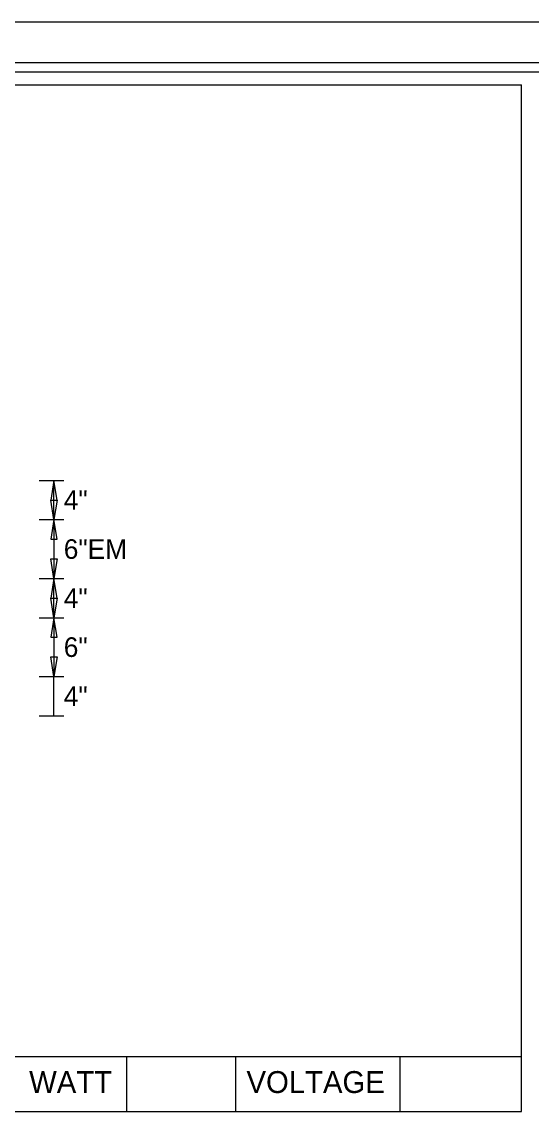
# Model space of a CAD drawing. Extents: x 1374 to 1480, y 568 to 638.
# Drawn here: x 1423.92 to 1428.25, y 595.3 to 604.64 of the extents above; entities that cross this region are included whole.
import ezdxf

# ---------------------------------------------------------------- set-up
doc = ezdxf.new("R2010")
doc.units = 0
for name, color, linetype in [('GSDims', 7, 'Continuous'), ('PlotBorder_dp', 7, 'Continuous'), ('SheetBorder_dp', 7, 'Continuous'), ('SheetLinesMisc2_dp', 7, 'Continuous'), ('TextMinor', 7, 'Continuous')]:
    doc.layers.add(name, color=color, linetype=linetype)

msp = doc.modelspace()

# ---------------------------------------------------------------- linework, layer by layer
at = {"layer": 'GSDims'}
for p, q in [((1424.0665, 600.7496), (1424.2748, 600.7496)), ((1424.0665, 600.7496), (1424.0665, 600.7496)), ((1424.1915, 600.4162), (1424.1915, 600.7496)), ((1424.0665, 600.4162), (1424.2748, 600.4162)), ((1424.0665, 600.4162), (1424.2748, 600.4162)), ((1424.1915, 600.4162), (1424.1915, 599.9162)), ((1424.0665, 599.9162), (1424.2748, 599.9162)), ((1424.0665, 599.9162), (1424.2748, 599.9162)), ((1424.1915, 599.5829), (1424.1915, 599.9162)), ((1424.0665, 599.5829), (1424.2748, 599.5829)), ((1424.0665, 599.5829), (1424.2748, 599.5829)), ((1424.1915, 599.5829), (1424.1915, 599.0829)), ((1424.0665, 599.0829), (1424.2748, 599.0829)), ((1424.0665, 599.0829), (1424.2748, 599.0829)), ((1424.1915, 598.7496), (1424.1915, 599.0829)), ((1424.0665, 598.7496), (1424.2748, 598.7496)), ((1424.0665, 598.7496), (1424.0665, 598.7496))]:
    msp.add_line(p, q, dxfattribs=at)
for points in [[(1424.1915, 600.7496), (1424.1637, 600.5829), (1424.2192, 600.5829)], [(1424.1915, 600.4162), (1424.1637, 600.5829), (1424.2192, 600.5829)], [(1424.1915, 600.4162), (1424.1637, 600.2496), (1424.2192, 600.2496)], [(1424.1915, 599.9162), (1424.1637, 600.0829), (1424.2192, 600.0829)], [(1424.1915, 599.9162), (1424.1637, 599.7496), (1424.2192, 599.7496)], [(1424.1915, 599.5829), (1424.1637, 599.7496), (1424.2192, 599.7496)], [(1424.1915, 599.5829), (1424.1637, 599.4162), (1424.2192, 599.4162)], [(1424.1915, 599.0829), (1424.1637, 599.2496), (1424.2192, 599.2496)]]:
    msp.add_lwpolyline(points, close=True, dxfattribs=at)
at = {"layer": 'PlotBorder_dp'}
msp.add_lwpolyline([(1400.0353, 568.2746), (1456.6475, 568.2746), (1456.6475, 604.6443), (1400.0353, 604.6443)], close=True, dxfattribs=at)
at = {"layer": 'SheetBorder_dp'}
msp.add_line((1401.9224, 604.3012), (1454.7604, 604.3012), dxfattribs=at)
at = {"layer": 'SheetLinesMisc2_dp'}
for p, q in [((1402.0156, 604.2202), (1454.6689, 604.2202)), ((1410.2556, 604.111), (1428.1633, 604.111)), ((1428.1633, 595.3881), (1428.1633, 604.111)), ((1410.2556, 595.8555), (1428.1633, 595.8555)), ((1424.808, 595.8555), (1424.808, 595.3881)), ((1425.7344, 595.8555), (1425.7344, 595.3881)), ((1427.1292, 595.8555), (1427.1292, 595.3881)), ((1410.2556, 595.3881), (1428.1633, 595.3881))]:
    msp.add_line(p, q, dxfattribs=at)

# ---------------------------------------------------------------- texts
at = {"layer": 'GSDims'}
for s, p in [('4"', (1424.2748, 600.4996)), ('6"EM', (1424.2748, 600.0829)), ('4"', (1424.2748, 599.6662)), ('6"', (1424.2748, 599.2496)), ('4"', (1424.2748, 598.8329))]:
    msp.add_text(s, height=0.16667, dxfattribs=at).set_placement(p)
at = {"layer": 'TextMinor'}
for s, p in [('WATT', (1423.9805, 595.5446)), ('VOLTAGE', (1425.8272, 595.5446))]:
    msp.add_text(s, height=0.18601, dxfattribs=at).set_placement(p)

doc.saveas('drawing.dxf')
